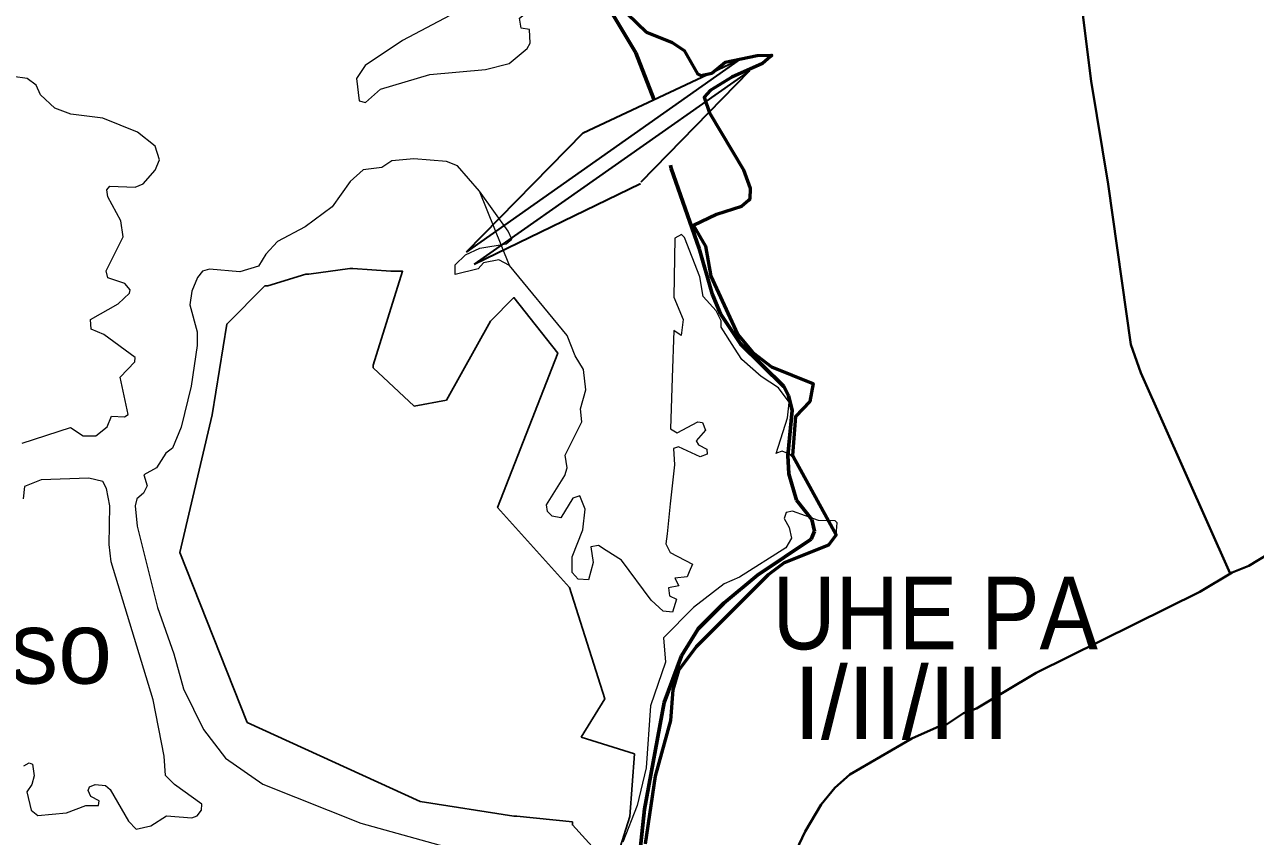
# Model space of a CAD drawing. Extents: x -1643653 to 4543381, y 1624270 to 13878484.
# Drawn here: x 583094 to 591570, y 8959416 to 8965010 of the extents above; entities that cross this region are included whole.
import ezdxf
from ezdxf.enums import TextEntityAlignment as Align

# ---------------------------------------------------------------- set-up
doc = ezdxf.new("R2010")
doc.units = 0
doc.header["$LTSCALE"] = 200
doc.linetypes.add('LONG_DASH_SHORT_DASH', pattern=[9.9, 6, -1.2, 1.5, -1.2])
for name, color, linetype, lineweight in [('12', 7, 'Continuous', 25), ('21', 7, 'Continuous', 25), ('25', 7, 'Continuous', 13), ('28', 7, 'Continuous', 53), ('60', 7, 'Continuous', 13), ('7', 7, 'LONG_DASH_SHORT_DASH', 60)]:
    doc.layers.add(name, color=color, linetype=linetype, lineweight=lineweight)
doc.layers.add('41', color=7, linetype='Continuous')
doc.layers.add('42', color=7, linetype='Continuous')

msp = doc.modelspace()

# ---------------------------------------------------------------- linework, layer by layer
at = {"layer": '12', "lineweight": 40}
for points in [[(590381.4, 8965077.2), (590437.7, 8964620.9), (590556.9, 8963909.5), (590712.3, 8962804.7), (590781.8, 8962609.4), (591396.4, 8961227.9)], [(587134, 8956453.8), (587843.6, 8957685.7), (587923.7, 8957988.5), (588169.9, 8958625.1), (588237, 8958904.7), (588304.1, 8959099.5), (588468, 8959448.9), (588578.9, 8959635.8), (588673.7, 8959750.1), (588777.5, 8959843.1), (589203.6, 8960089.7), (589393.4, 8960175.8), (589428.5, 8960178.5), (589560.1, 8960264.6), (589648.9, 8960297.2), (590059.4, 8960543.5), (591188.1, 8961101.4), (591408.7, 8961235.4), (591525.3, 8961280.9), (591868.7, 8961488.1), (592154.1, 8961587.2), (592311.1, 8961655)]]:
    msp.add_lwpolyline(points, dxfattribs=at)
at = {"layer": '21'}
for points in [[(587068.3, 8959273), (586866.5, 8959495), (586866.5, 8959515.2), (586483.1, 8959555.5), (586463, 8959555.5), (585817.3, 8959656.5), (584626.8, 8960201.4), (584162.8, 8961372.1), (584384.7, 8962320.7), (584485.6, 8962946.4), (584747.9, 8963208.8), (584768.1, 8963208.8), (585030.4, 8963289.5), (585050.6, 8963289.5), (585333, 8963329.9), (585353.2, 8963329.9), (585615.5, 8963309.7), (585655.9, 8963309.7), (585676, 8963309.7), (585696.2, 8963309.7), (585494.5, 8962663.8), (585494.5, 8962643.7), (585776.9, 8962381.3), (585998.9, 8962421.6), (586301.5, 8962966.6), (586463, 8963128.1), (586765.6, 8962744.6), (586351.3, 8961682.2), (586846.3, 8961129.9), (587088.5, 8960362.9), (586927, 8960100.5)], [(586927, 8960100.5), (587293.7, 8959984.2), (587261.8, 8959553.8), (587182.2, 8959298.7), (587110, 8958948.6), (587182.2, 8958662.7), (587182.2, 8958533.5), (587309.6, 8958437.9), (588138.3, 8958278.5)]]:
    msp.add_lwpolyline(points, dxfattribs=at)
at = {"layer": '25', "lineweight": 35}
for p, q in [((588022.6, 8964770.6), (586135.6, 8963442.6)), ((586940.7, 8964263.4), (588022.6, 8964770.6)), ((588084.7, 8964692), (586189.9, 8963358.5)), ((587339.3, 8963925.5), (588084.7, 8964692)), ((586940.7, 8964263.4), (586135.6, 8963442.6)), ((586189.9, 8963358.5), (587335.7, 8963913.8))]:
    msp.add_line(p, q, dxfattribs=at)
at = {"layer": '25'}
msp.add_lwpolyline([(585439, 8964728.2), (585379.4, 8964639), (585398.5, 8964484), (585440.9, 8964473.3), (585545, 8964564.5), (585884.6, 8964666.3), (586267.5, 8964700.5), (586430.8, 8964740.8), (586553.9, 8964845), (586575.2, 8964881), (586570.7, 8964976.5), (586513.6, 8964985.3), (586501.3, 8965053.3), (586579.7, 8965116.9), (586670.6, 8965163.4), (586903.9, 8965197.4), (586919.2, 8965218.6), (586866.7, 8965384.8), (586876.8, 8965441.6), (586860, 8965477.5), (586435.1, 8965293.1), (585696.3, 8964900.4)], close=True, dxfattribs=at)
msp.add_lwpolyline([(585439, 8964728.2), (585379.4, 8964639), (585398.5, 8964484), (585440.9, 8964473.3), (585545, 8964564.5), (585884.6, 8964666.3), (586267.5, 8964700.5), (586430.8, 8964740.8), (586553.9, 8964845), (586575.2, 8964881), (586570.7, 8964976.5), (586513.6, 8964985.3), (586501.3, 8965053.3), (586579.7, 8965116.9), (586670.6, 8965163.4), (586903.9, 8965197.4), (586919.2, 8965218.6), (586866.7, 8965384.8), (586876.8, 8965441.6), (586860, 8965477.5), (586435.1, 8965293.1), (585696.3, 8964900.4)], close=True, dxfattribs=at)
for points in [[(587244.3, 8965087.2), (587376.1, 8964957.5), (587554.3, 8964887.4), (587635.2, 8964832.1), (587726.7, 8964670.8), (587750.6, 8964658), (587826.4, 8964675), (587917.9, 8964751.3), (588138.8, 8964796.3), (588239.8, 8964798.6), (588239.8, 8964798.6), (588231, 8964790.9)], [(587244.3, 8965087.2), (587376.1, 8964957.5), (587554.3, 8964887.4), (587635.2, 8964832.1), (587678.5, 8964757.6)], [(588231, 8964790.9), (588174.2, 8964740.5), (587964.7, 8964647.4), (587813.9, 8964556), (587773.6, 8964509.6), (587809.5, 8964400.9), (588045.3, 8964009.8), (588090.5, 8963883.4), (588087.9, 8963805.8), (588079.5, 8963798.7)], [(583076.4, 8962125.7), (583410.3, 8962234), (583497.2, 8962176.9), (583584.3, 8962176.9), (583662.8, 8962238.5), (583692.8, 8962310.5), (583781.6, 8962306.4), (583807.2, 8962323.5), (583752.2, 8962580.2), (583853.2, 8962685.6), (583854, 8962716.3), (583639.8, 8962873.4), (583552.7, 8962911.8), (583548.2, 8962977.4), (583737.5, 8963086.2), (583815.2, 8963159.7), (583820, 8963181), (583784.2, 8963226), (583667.3, 8963264.5), (583654.7, 8963312.4), (583773.3, 8963547.2), (583756.3, 8963657.4), (583667.3, 8963822.9), (583661, 8963870), (583680, 8963897.4), (583854.1, 8963889), (583909.5, 8963912.6), (583992, 8964005.7), (584023.8, 8964077.5), (583992.3, 8964171.2), (583871.3, 8964269), (583632.9, 8964364.8), (583412.2, 8964392.4), (583302.1, 8964434.8), (583202.2, 8964526), (583174.1, 8964592.2), (583110.6, 8964638.7), (583013.2, 8964651.5)], [(583076.4, 8962125.7), (583410.3, 8962234), (583497.2, 8962176.9), (583584.3, 8962176.9), (583662.8, 8962238.5), (583692.8, 8962310.5), (583781.6, 8962306.4), (583807.2, 8962323.5), (583752.2, 8962580.2), (583853.2, 8962685.6), (583854, 8962716.3), (583639.8, 8962873.4), (583552.7, 8962911.8), (583548.2, 8962977.4), (583737.5, 8963086.2), (583815.2, 8963159.7), (583820, 8963181), (583784.2, 8963226), (583667.3, 8963264.5), (583654.7, 8963312.4), (583773.3, 8963547.2), (583756.3, 8963657.4), (583667.3, 8963822.9), (583661, 8963870), (583680, 8963897.4), (583854.1, 8963889), (583909.5, 8963912.6), (583992, 8964005.7), (584023.8, 8964077.5), (583992.3, 8964171.2), (583871.3, 8964269), (583632.9, 8964364.8), (583412.2, 8964392.4), (583302.1, 8964434.8), (583202.2, 8964526), (583174.1, 8964592.2), (583110.6, 8964638.7), (583013.2, 8964651.5)], [(587773.6, 8964509.6), (587809.5, 8964400.9), (588045.3, 8964009.8), (588090.5, 8963883.4), (588087.9, 8963805.8), (588079.5, 8963798.7)], [(587098.4, 8961386.8), (587045, 8961420.4), (586993.8, 8961411.8), (587008.6, 8961303.5), (586976.2, 8961182.7), (586906.7, 8961189.1), (586864.3, 8961233.5), (586864.2, 8961341.7), (586938.6, 8961529.2), (586953.1, 8961669.7), (586916.8, 8961762.6), (586868.3, 8961747.5), (586787.2, 8961611.7), (586725.9, 8961622.5), (586694.3, 8961654.3), (586687.9, 8961700.7), (586815.2, 8961902.8), (586830.2, 8961956.5), (586815.4, 8962043.2), (586930, 8962273.3), (586921.5, 8962361.5), (586957.6, 8962493.3), (586943, 8962632.7), (586885.4, 8962727), (586830, 8962867.4), (586432.9, 8963349.4), (586358.6, 8963389.7), (586254.6, 8963368.5), (586216.2, 8963326.1), (586059.1, 8963288.1), (586058.9, 8963353.2), (586131.1, 8963423.6), (586229.2, 8963469.6), (586410.8, 8963500), (586449.8, 8963530), (586424.4, 8963587.3), (586226.9, 8963861.3), (586073.9, 8964035.5), (585999.3, 8964065.2), (585774.7, 8964084.4), (585623.6, 8964071.6), (585553.5, 8964025), (585426.1, 8964010), (585334.9, 8963929.5), (585211.3, 8963752.8), (585026.9, 8963615.1), (584835.5, 8963515.1), (584755, 8963428.2), (584703.5, 8963345.2), (584575.7, 8963306.9), (584575.7, 8963306.9), (584367.9, 8963323.8), (584319.4, 8963311.1), (584283.8, 8963267.3), (584244.9, 8963172.8), (584232.2, 8963079.6), (584283.2, 8962892.7), (584283.2, 8962799.2), (584240.7, 8962518.8), (584172.1, 8962236.3), (584113.2, 8962091.9), (584066.4, 8962055.5), (584002.7, 8961956), (583913.8, 8961907.2), (583936.8, 8961830.6), (583913.5, 8961781.7), (583866.6, 8961740.8), (583856.2, 8961694.6), (583869, 8961554.4), (584009.2, 8960993.4), (584121.2, 8960674.7), (584187.7, 8960432.6), (584325.6, 8960152.6), (584476.5, 8959954.9), (584733.5, 8959776.4), (585408.8, 8959506.7), (586028.5, 8959334.8)], [(587098.4, 8961386.8), (587045, 8961420.4), (586993.8, 8961411.8), (587008.6, 8961303.5), (586976.2, 8961182.7), (586906.7, 8961189.1), (586864.3, 8961233.5), (586864.2, 8961341.7), (586938.6, 8961529.2), (586953.1, 8961669.7), (586916.8, 8961762.6), (586868.3, 8961747.5), (586787.2, 8961611.7), (586725.9, 8961622.5), (586694.3, 8961654.3), (586687.9, 8961700.7), (586815.2, 8961902.8), (586830.2, 8961956.5), (586815.4, 8962043.2), (586930, 8962273.3), (586921.5, 8962361.5), (586957.6, 8962493.3), (586943, 8962632.7), (586885.4, 8962727), (586830, 8962867.4), (586432.9, 8963349.4), (586226.9, 8963861.3), (586073.9, 8964035.5), (585999.3, 8964065.2), (585774.7, 8964084.4), (585623.6, 8964071.6), (585553.5, 8964025), (585426.1, 8964010), (585334.9, 8963929.5), (585211.3, 8963752.8), (585026.9, 8963615.1), (584835.5, 8963515.1), (584755, 8963428.2), (584703.5, 8963345.2), (584575.7, 8963306.9), (584575.7, 8963306.9), (584367.9, 8963323.8), (584319.4, 8963311.1), (584283.8, 8963267.3), (584244.9, 8963172.8), (584232.2, 8963079.6), (584283.2, 8962892.7), (584283.2, 8962799.2), (584240.7, 8962518.8), (584172.1, 8962236.3), (584113.2, 8962091.9), (584066.4, 8962055.5), (584002.7, 8961956), (583913.8, 8961907.2), (583936.8, 8961830.6), (583913.5, 8961781.7), (583866.6, 8961740.8), (583856.2, 8961694.6), (583869, 8961554.4), (584009.2, 8960993.4), (584121.2, 8960674.7), (584187.7, 8960432.6), (584325.6, 8960152.6), (584476.5, 8959954.9), (584733.5, 8959776.4), (585408.8, 8959506.7), (586028.5, 8959334.8)], [(588079.5, 8963798.7), (588030.2, 8963757.2), (587858.5, 8963700), (587699.1, 8963625.3), (587781.9, 8963483), (587820, 8963275.3), (588002, 8962877.1), (588002, 8962877.1), (588108.8, 8962750.5), (588236.2, 8962650.7), (588523, 8962536.8)], [(588079.5, 8963798.7), (588030.2, 8963757.2), (587858.5, 8963700), (587699.1, 8963625.3), (587781.9, 8963483), (587820, 8963275.3), (588002, 8962877.1), (588002, 8962877.1), (588108.8, 8962750.5), (588236.2, 8962650.7), (588523, 8962536.8)], [(587982.8, 8962779.3), (587890.3, 8962924.4), (587890.1, 8962969.1), (587856.3, 8963036.9), (587766.9, 8963135.1), (587743.6, 8963270.8), (587637.1, 8963543.2), (587617, 8963563.8), (587571.7, 8963538.4), (587565.1, 8963131.3), (587628.8, 8962977.9), (587616.1, 8962866.9), (587565.4, 8962902.1), (587554.1, 8962576.4)], [(587982.8, 8962779.3), (587890.3, 8962924.4), (587890.1, 8962969.1), (587856.3, 8963036.9), (587766.9, 8963135.1), (587743.6, 8963270.8), (587637.1, 8963543.2), (587617, 8963563.8), (587571.7, 8963538.4), (587565.1, 8963131.3), (587628.8, 8962977.9), (587616.1, 8962866.9), (587565.4, 8962902.1), (587554.1, 8962576.4)], [(588354.5, 8962361.1), (588359.4, 8962408.8), (588285.5, 8962505.9), (588167, 8962584.2), (588032.3, 8962701.8), (587982.8, 8962779.3)], [(588354.5, 8962361.1), (588359.4, 8962408.8), (588285.5, 8962505.9), (588167, 8962584.2), (588032.3, 8962701.8), (587982.8, 8962779.3)], [(587554.1, 8962576.4), (587541.8, 8962223.9), (587588.7, 8962196), (587730.7, 8962272.2), (587762.7, 8962269), (587781.7, 8962215.1)], [(587554.1, 8962576.4), (587541.8, 8962223.9), (587588.7, 8962196), (587730.7, 8962272.2), (587762.7, 8962269), (587781.7, 8962215.1)], [(588523, 8962536.8), (588524.4, 8962536.2), (588501.9, 8962412.8), (588402.2, 8962308.3), (588381.1, 8962040.8), (588376.4, 8962042.8)], [(588523, 8962536.8), (588524.4, 8962536.2), (588501.9, 8962412.8), (588402.2, 8962308.3), (588381.1, 8962040.8), (588376.4, 8962042.8)], [(588271.6, 8962055.8), (588270.1, 8962055.2), (588348.1, 8962299.3), (588354.5, 8962361.1)], [(588271.6, 8962055.8), (588270.1, 8962055.2), (588348.1, 8962299.3), (588354.5, 8962361.1)], [(587781.7, 8962215.1), (587781.7, 8962215.1), (587718.2, 8962140.9), (587735, 8962113.3), (587792.4, 8962083.3), (587794.6, 8962050), (587745.5, 8962032.4), (587597.2, 8962100.2), (587563.1, 8962089.5), (587569.5, 8961975.7), (587540.2, 8961707.3), (587517.7, 8961501.6)], [(587781.7, 8962215.1), (587781.7, 8962215.1), (587718.2, 8962140.9), (587735, 8962113.3), (587792.4, 8962083.3), (587794.6, 8962050), (587745.5, 8962032.4), (587597.2, 8962100.2), (587563.1, 8962089.5), (587569.5, 8961975.7), (587540.2, 8961707.3), (587517.7, 8961501.6)], [(588376.4, 8962042.8), (588311.2, 8962069.4), (588271.6, 8962055.8), (588271.7, 8962060.3), (588271.6, 8962055.8)], [(588376.4, 8962042.8), (588311.2, 8962069.4), (588271.6, 8962055.8), (588271.7, 8962060.3), (588271.6, 8962055.8)], [(583089.5, 8959901.9), (583125.3, 8959922.9), (583148.8, 8959914.2), (583159.4, 8959833.8), (583144.6, 8959774.5), (583108.6, 8959723.3), (583108.6, 8959723.3), (583138.3, 8959595.9), (583184.5, 8959559.9), (583382, 8959578.8), (583514.4, 8959627.7), (583603.4, 8959628), (583607.5, 8959661.8), (583550.2, 8959691.6), (583531.3, 8959731.8), (583541.6, 8959757), (583580.3, 8959774.3), (583651.7, 8959765.9), (583684, 8959740.2), (583809.5, 8959521.5), (583862.6, 8959466.3), (583962.4, 8959487.6), (584070.6, 8959557.6), (584244.7, 8959542.8), (584281, 8959557.7), (584312.8, 8959595.8), (584315, 8959638.2), (584126, 8959774.3), (584064.3, 8959836.4), (584055.9, 8959969.5), (583979.3, 8960356.6), (583690.5, 8961308.2), (583675.7, 8961427), (583679.9, 8961694.8), (583656.7, 8961812.9), (583631.9, 8961861.4), (583535.2, 8961883.6), (583208.6, 8961873.1), (583093.8, 8961826.3), (583082.9, 8961741.4)], [(583089.5, 8959901.9), (583125.3, 8959922.9), (583148.8, 8959914.2), (583159.4, 8959833.8), (583144.6, 8959774.5), (583108.6, 8959723.3), (583108.6, 8959723.3), (583138.3, 8959595.9), (583184.5, 8959559.9), (583382, 8959578.8), (583514.4, 8959627.7), (583603.4, 8959628), (583607.5, 8959661.8), (583550.2, 8959691.6), (583531.3, 8959731.8), (583541.6, 8959757), (583580.3, 8959774.3), (583651.7, 8959765.9), (583684, 8959740.2), (583809.5, 8959521.5), (583862.6, 8959466.3), (583962.4, 8959487.6), (584070.6, 8959557.6), (584244.7, 8959542.8), (584281, 8959557.7), (584312.8, 8959595.8), (584315, 8959638.2), (584126, 8959774.3), (584064.3, 8959836.4), (584055.9, 8959969.5), (583979.3, 8960356.6), (583690.5, 8961308.2), (583675.7, 8961427), (583679.9, 8961694.8), (583656.7, 8961812.9), (583631.9, 8961861.4), (583535.2, 8961883.6), (583208.6, 8961873.1), (583093.8, 8961826.3), (583082.9, 8961741.4)], [(587368.2, 8959365.5), (587437, 8959830.7), (587541.6, 8960215), (587558.8, 8960425), (587596.7, 8960558.6), (587717.4, 8960723.2), (588213.5, 8961217.2), (588323.7, 8961300.9), (588630.6, 8961421.7), (588681.9, 8961493.8), (588689.2, 8961575.7), (588675.2, 8961590.7), (588561, 8961592.8), (588381.1, 8961656.2), (588338.6, 8961648.6), (588325.4, 8961606.6), (588359, 8961544.8), (588373.9, 8961471.3), (588335.7, 8961403.9), (588018, 8961201.6), (587911.6, 8961156.7), (587701, 8960992.4), (587493.3, 8960783.2), (587506.9, 8960616.2), (587403.7, 8960314.5), (587373.8, 8959887.7), (587311.1, 8959628.3), (587213.9, 8959375.4)], [(587517.7, 8961501.6), (587510, 8961431.2), (587539.9, 8961371.6), (587692.7, 8961292.6), (587670.8, 8961239.2)], [(587517.7, 8961501.6), (587510, 8961431.2), (587539.9, 8961371.6), (587692.7, 8961292.6), (587670.8, 8961239.2)], [(587670.8, 8961239.2), (587656.4, 8961204.1), (587570.6, 8961194.6), (587599.2, 8961141.8), (587527.1, 8961129.4), (587535.4, 8961074.6), (587582.5, 8961050.1), (587556.1, 8960961.2), (587491.1, 8960968.1), (587408.1, 8961044.4), (587205.3, 8961319.5), (587098.4, 8961386.8)], [(587670.8, 8961239.2), (587656.4, 8961204.1), (587570.6, 8961194.6), (587599.2, 8961141.8), (587527.1, 8961129.4), (587535.4, 8961074.6), (587582.5, 8961050.1), (587556.1, 8960961.2), (587491.1, 8960968.1), (587408.1, 8961044.4), (587205.3, 8961319.5), (587098.4, 8961386.8)]]:
    msp.add_lwpolyline(points, dxfattribs=at)
at = {"layer": '28'}
for points in [[(587244.3, 8965087.2), (587376.1, 8964957.5), (587554.3, 8964887.4), (587635.2, 8964832.1), (587726.7, 8964670.8), (587750.6, 8964658), (587826.4, 8964675), (587917.9, 8964751.3), (588138.8, 8964796.3), (588239.8, 8964798.6), (588239.8, 8964798.6), (588231, 8964790.9)], [(588231, 8964790.9), (588174.2, 8964740.5), (587964.7, 8964647.4), (587813.9, 8964556), (587773.6, 8964509.6), (587809.5, 8964400.9), (588045.3, 8964009.8), (588090.5, 8963883.4), (588087.9, 8963805.8), (588079.5, 8963798.7)], [(588079.5, 8963798.7), (588030.2, 8963757.2), (587858.5, 8963700), (587699.1, 8963625.3), (587781.9, 8963483), (587820, 8963275.3), (588002, 8962877.1), (588002, 8962877.1), (588108.8, 8962750.5), (588236.2, 8962650.7), (588523, 8962536.8)], [(588523, 8962536.8), (588524.4, 8962536.2), (588501.9, 8962412.8), (588402.2, 8962308.3), (588381.1, 8962040.8), (588373.5, 8962049.1)], [(588373.5, 8962049.1), (588387.5, 8962034), (588681.9, 8961493.8), (588630.6, 8961421.7), (588323.7, 8961300.9), (588213.5, 8961217.2), (587717.4, 8960723.2), (587596.7, 8960558.6), (587558.8, 8960425), (587541.6, 8960215), (587437, 8959830.7), (587368.2, 8959365.5)]]:
    msp.add_lwpolyline(points, dxfattribs=at)
at = {"layer": '60', "lineweight": 25}
msp.add_spline([(814781, 9009175.5), (814787.2, 9009173.4), (814796.9, 9009173.4), (814799.4, 9009172.4), (814805.1, 9009174.5), (814805.6, 9009176.5), (814811.7, 9009179.5), (814811.7, 9009179.5), (814801.5, 9009181), (814790.7, 9009181.5), (814784.1, 9009183.1), (814777.4, 9009185.1), (814778.4, 9009175.5)], degree=3, dxfattribs=at)
at = {"layer": '7'}
for points in [[(583174.4, 8969966), (583327.9, 8969505.4), (583474.7, 8969160.4), (583725.5, 8968684.8), (583883.2, 8968539.9), (583982.9, 8968403.5), (584146.9, 8968235.1), (584624.8, 8967616.6), (584992.2, 8967072.1), (585186.8, 8966825.7), (585377.2, 8966655.9), (585748.8, 8966438.6), (585960.5, 8966257.3), (586351.6, 8965976.8), (586551, 8965796.4), (587006.6, 8965310.9), (587303.1, 8964815.2), (587426.7, 8964495.3)], [(587540.9, 8964040.5), (587545.5, 8964019), (587739.9, 8963466), (587828.5, 8963155), (587886.8, 8963016.8), (588023, 8962809.1), (588321.3, 8962515.1), (588353.7, 8962454.8), (588379.7, 8962350), (588349.5, 8962039.7), (588356.1, 8961913.4), (588409.9, 8961732.7), (588515.9, 8961598.5), (588533, 8961520.2), (588511.4, 8961464.3), (588140, 8961216), (587908.2, 8961023.1), (587733.4, 8960846.2), (587616.5, 8960660), (587498.3, 8960337.4), (587362.2, 8959603), (587314, 8959147.2), (587303.2, 8958935.8), (587310.7, 8958873)]]:
    msp.add_lwpolyline(points, dxfattribs=at)

# ---------------------------------------------------------------- texts
at = {"layer": '41'}
msp.add_text('Paulo Afonso', height=500, dxfattribs=at).set_placement((581707.6, 8960468.8), align=Align.CENTER)
at = {"layer": '42', "width": 0.9}
msp.add_text('UHE PA', height=500, dxfattribs=at).set_placement((589364.5, 8960705), align=Align.CENTER)
at = {"layer": '42'}
msp.add_text('I/II/III', height=500, dxfattribs=at).set_placement((589134.4, 8960086.2), align=Align.CENTER)

doc.saveas('drawing.dxf')
